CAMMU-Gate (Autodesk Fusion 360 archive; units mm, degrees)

design "CAMMU-Gate" references "Slider T-Nut for 2020 - M5", "MR63ZZ"
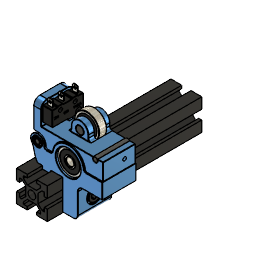
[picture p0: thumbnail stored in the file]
description: Part Number
part number: CAMMU-Linear-Rail-Lead-Screw
part number: Endstop Limit Switch v1
part number: Screw
part number: Brass body
part number: Brass NUT
part number: 625Z_1
named bodies: "Gate bottom (NEW)", "Gate top (NEW)"

design "MR63ZZ"
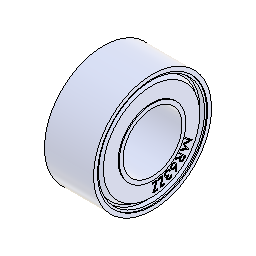
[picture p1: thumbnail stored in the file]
description: STEP AP214
part number: MR63ZZ
description: Part Number
part number: outer shell - mz63zz
part number: inner shell - mz63zz
part number: 1mm ball bearing sphere
part number: MR63ZZ - seal
base_feature "Base Feature1"
base_feature "Base Feature1"
base_feature "Base Feature1"
base_feature "Base Feature1"
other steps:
create_component "CreateComponent1"
create_component "CreateComponent2"
create_component "CreateComponent3"
create_component "CreateComponent4"

design "Slider T-Nut for 2020 - M5"
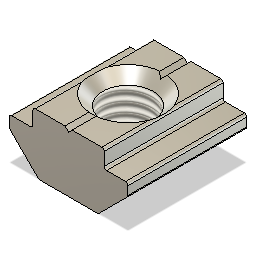
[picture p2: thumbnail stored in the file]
sketch "Sketch1"
  dimension "d1" = 10
  dimension "d4" = 5
  dimension "d5" = 45
  dimension "d6" = 1
  dimension "d7" = 5
  dimension "d8" = 6
  dimension "d9" = 2
  dimension "d10" = 2
  dimension "d12" = 45
  dimension "d13" = 0.3
  dimension "d14" = 5
  dimension "d15" = 1.5
  dimension "d16" = 0.2
extrude "Extrude1" new body sketch "Sketch1" blind 10
hole "Hole1" HoleDepth 5.834 HoleDiameter 4.234 TipAngle 180 CSDiameter 6 CSAngle 90 RefDim1 5 RefDim2 5
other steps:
thread "Thread1"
